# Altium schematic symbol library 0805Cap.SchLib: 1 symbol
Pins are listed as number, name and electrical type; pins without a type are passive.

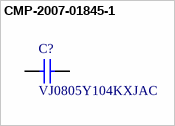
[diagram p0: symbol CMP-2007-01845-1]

## CMP-2007-01845-1
designator C?, comment VJ0805Y104KXJAC
Manufacturer: Vitramon
footprint CAPC2013X145X48NL20T23 (Chip Capacitor, 2-Leads, Body 2.00x1.25mm, IPC Medium Density)
footprint CAPC2013X145X48LL20T23 (Chip Capacitor, 2-Leads, Body 2.00x1.25mm, IPC High Density)
footprint CAPC2013X145X48ML20T23 (Chip Capacitor, 2-Leads, Body 2.00x1.25mm, IPC Low Density)
pins: 1, 2
1 alternate drawing of the same symbol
